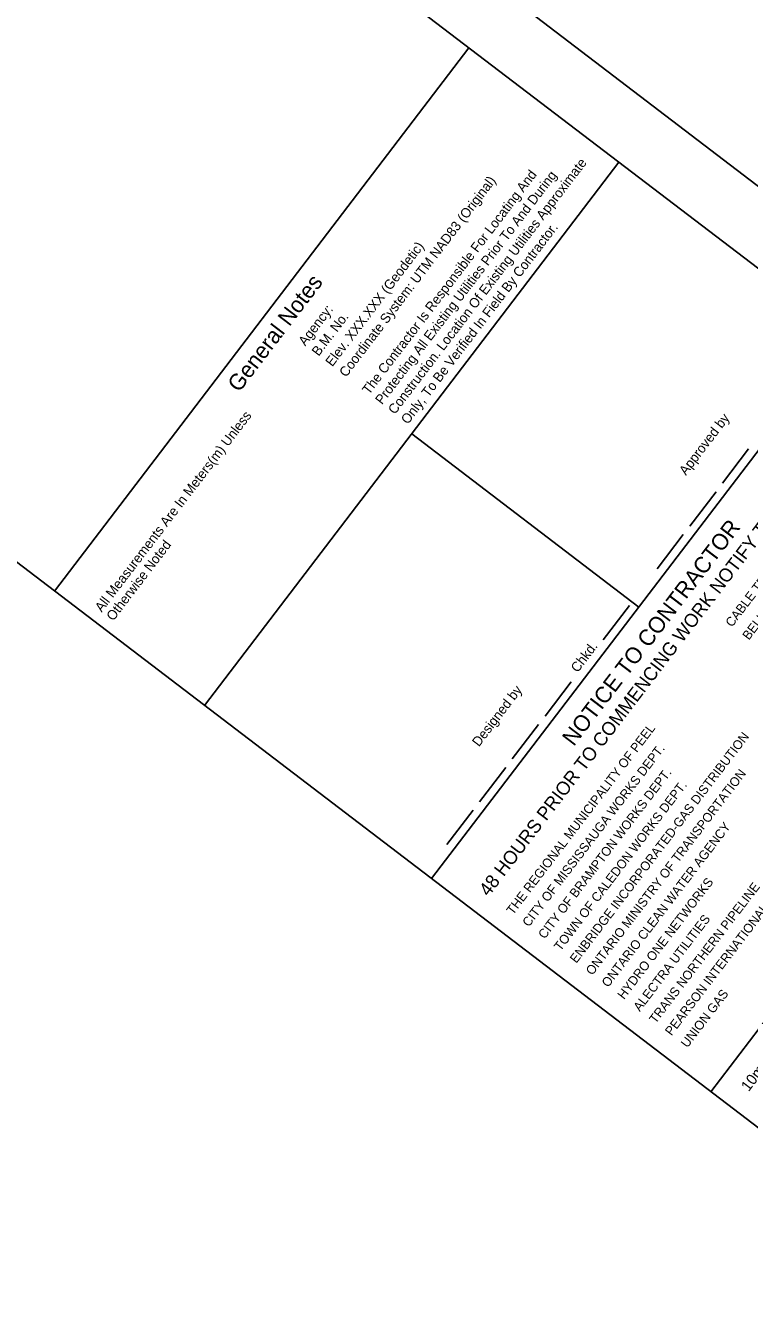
# Model space of a CAD drawing. Extents: x 599744 to 600217, y 4827560 to 4828065.
# Drawn here: x 600064.4 to 600131.6, y 4827854.2 to 4827973.4 of the extents above; entities that cross this region are included whole.
import ezdxf

# ---------------------------------------------------------------- set-up
doc = ezdxf.new("R2010")
doc.units = 0
for name, color, linetype in [('G-ANNO-BAR', 7, 'Continuous'), ('G-ANNO-STMP', 7, 'Continuous'), ('G-ANNO-TEXT', 7, 'Continuous'), ('G-TTLB-OTLN', 7, 'Continuous'), ('G-TTLB-OTLN-PB', 7, 'Continuous')]:
    doc.layers.add(name, color=color, linetype=linetype)

msp = doc.modelspace()

# ---------------------------------------------------------------- linework, layer by layer
at = {"layer": 'G-ANNO-STMP'}
for p, q in [((600129.11, 4827930.92), (600131.54, 4827934.1)), ((600126.08, 4827926.94), (600128.51, 4827930.12)), ((600123.05, 4827922.97), (600125.47, 4827926.15)), ((600118.04, 4827916.4), (600120.47, 4827919.58)), ((600112.64, 4827909.32), (600115.06, 4827912.5)), ((600109.6, 4827905.35), (600112.03, 4827908.53)), ((600106.57, 4827901.37), (600109, 4827904.55)), ((600103.54, 4827897.4), (600105.97, 4827900.58))]:
    msp.add_line(p, q, dxfattribs=at)
at = {"layer": 'G-TTLB-OTLN'}
for p, q in [((599997.48, 4828053.79), (600211.01, 4827890.89)), ((600067.13, 4827920.91), (600105.58, 4827971.32)), ((600119.5, 4827960.71), (600081.04, 4827910.3)), ((600172.55, 4827840.49), (600019.56, 4827957.2)), ((600140.56, 4827944.63), (600102.11, 4827894.23)), ((600100.27, 4827935.5), (600121.34, 4827919.43)), ((600166.48, 4827924.86), (600128.03, 4827874.45))]:
    msp.add_line(p, q, dxfattribs=at)
at = {"layer": 'G-TTLB-OTLN-PB'}
msp.add_lwpolyline([(599961.6, 4827559.69), (600216.77, 4827894.16), (599999.1, 4828060.21), (599743.94, 4827725.74)], close=True, dxfattribs=at)

# ---------------------------------------------------------------- texts
at = {"layer": 'G-ANNO-BAR'}
msp.add_text('10m', height=1, rotation=52.6603, dxfattribs=at).set_placement((600131.54, 4827874.41))
at = {"layer": 'G-ANNO-STMP'}
for s, p in [('Approved by', (600125.72, 4827931.59)), ('Chkd.', (600115.67, 4827913.29)), ('Designed by', (600106.51, 4827906.41))]:
    msp.add_text(s, height=0.9, rotation=52.6603, dxfattribs=at).set_placement(p)
at = {"layer": 'G-ANNO-TEXT'}
for s, height, p in [('Construction. Location Of Existing Utilities Approximate ', 0.9, (600098.71, 4827937.25)), ('Coordinate System: UTM NAD83 (Original)', 0.9, (600094.18, 4827940.7)), ('The Contractor Is Responsible For Locating And ', 0.9, (600096.31, 4827939.08)), ('Protecting All Existing Utilities Prior To And During ', 0.9, (600097.52, 4827938.16)), ('Only, To Be Verified In Field By Contractor.', 0.9, (600099.91, 4827936.33)), ('Elev. XXX.XXX (Geodetic)', 0.9, (600092.9, 4827941.68)), ('General Notes', 1.5, (600084.25, 4827939.28)), ('Agency: ', 0.9, (600090.39, 4827943.6)), ('B.M. No. ', 0.9, (600091.63, 4827942.65)), ('All Measurements Are In Meters(m) Unless ', 0.9, (600071.5, 4827918.9)), ('CABLE TELEVISION/FIBREOPTIC PROVIDERS:', 0.85, (600129.99, 4827917.51)), ('48 HOURS PRIOR TO COMMENCING WORK NOTIFY THE FOLLOWING', 1.25, (600107.4, 4827892.5)), ('NOTICE TO CONTRACTOR', 1.5, (600115.31, 4827906.44)), ('Otherwise Noted', 0.9, (600072.57, 4827918.08)), ('BELL CANADA', 0.85, (600131.56, 4827916.31)), ('THE REGIONAL MUNICIPALITY OF PEEL', 0.85, (600109.67, 4827890.81)), ('ENBRIDGE INCORPORATED-GAS DISTRIBUTION', 0.85, (600115.55, 4827886.32)), ('CITY OF MISSISSAUGA WORKS DEPT.', 0.85, (600111.14, 4827889.69)), ('CITY OF BRAMPTON WORKS DEPT.', 0.85, (600112.61, 4827888.57)), ('ONTARIO MINISTRY OF TRANSPORTATION', 0.85, (600117.03, 4827885.2)), ('TOWN OF CALEDON WORKS DEPT.', 0.85, (600114.08, 4827887.45)), ('PEARSON INTERNATIONAL FUEL FACILITIES CORP.', 0.85, (600124.38, 4827879.59)), ('ONTARIO CLEAN WATER AGENCY', 0.85, (600118.5, 4827884.08)), ('HYDRO ONE NETWORKS', 0.85, (600119.97, 4827882.96)), ('TRANS NORTHERN PIPELINE', 0.85, (600122.91, 4827880.71)), ('ALECTRA UTILITIES', 0.85, (600121.44, 4827881.84)), ('UNION GAS', 0.85, (600125.85, 4827878.47))]:
    msp.add_text(s, height=height, rotation=52.6603, dxfattribs=at).set_placement(p)

doc.saveas('drawing.dxf')
